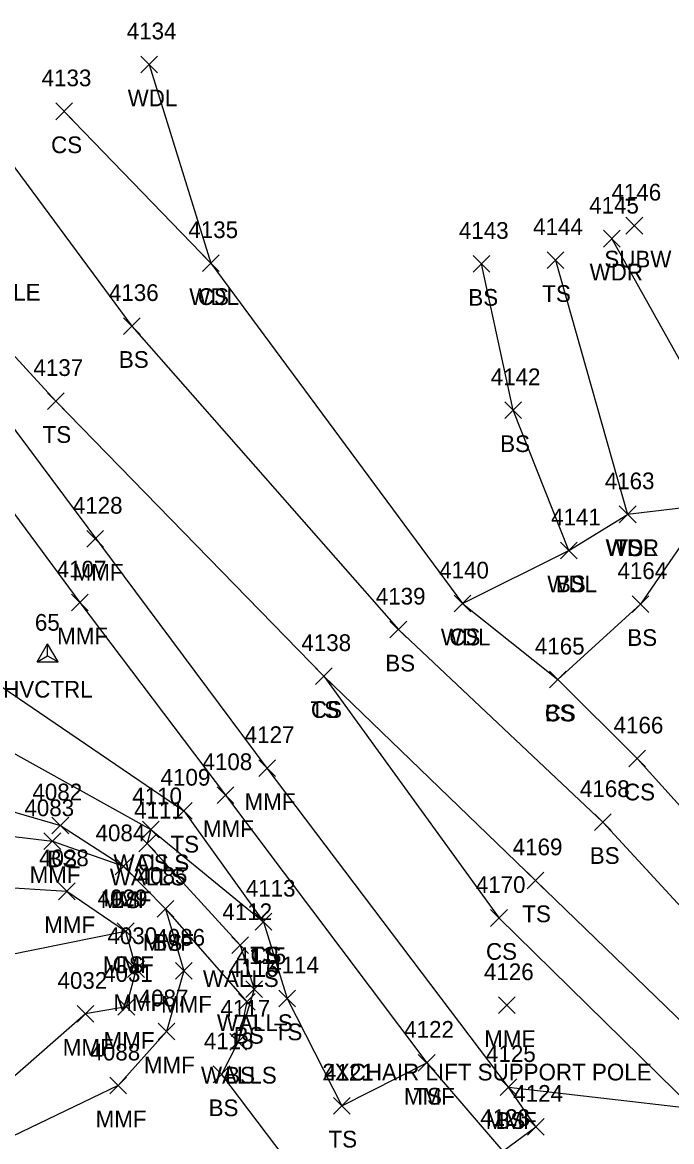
# Model space of a CAD drawing. Extents: x 49137 to 50946, y 9590 to 10709.
# Drawn here: x 50023.9 to 50101.6, y 10574.6 to 10708.5 of the extents above; entities that cross this region are included whole.
import ezdxf

# ---------------------------------------------------------------- set-up
doc = ezdxf.new("R2010")
doc.units = 0
for name, color, linetype in [('C_A', 7, 'Continuous'), ('C_I', 7, 'Continuous'), ('CPSM', 7, 'Continuous'), ('L_A', 7, 'Continuous'), ('L_C', 7, 'Continuous'), ('L_I', 7, 'Continuous'), ('L_TIC', 7, 'Continuous'), ('LAWA', 7, 'Continuous'), ('LDEFAULT', 7, 'Continuous'), ('LELB', 7, 'Continuous'), ('LWS', 7, 'Continuous'), ('U_A', 7, 'Continuous'), ('U_I', 7, 'Continuous'), ('U_TIC', 7, 'Continuous')]:
    doc.layers.add(name, color=color, linetype=linetype)

msp = doc.modelspace()

# ---------------------------------------------------------------- linework, layer by layer
at = {"layer": 'CPSM'}
for p, q in [((50025.71, 10632.03), (50026.96, 10634.2)), ((50028.21, 10632.03), (50026.96, 10634.2)), ((50026.96, 10632.75), (50026.96, 10634.2)), ((50025.71, 10632.03), (50026.96, 10632.75)), ((50025.71, 10632.03), (50028.21, 10632.03)), ((50026.96, 10632.75), (50026.96, 10632.75)), ((50026.96, 10632.75), (50028.21, 10632.03))]:
    msp.add_line(p, q, dxfattribs=at)
at = {"layer": 'L_TIC'}
for points in [[(50038.12, 10702.48), (50040.12, 10704.48)], [(50040.12, 10702.48), (50038.12, 10704.48)], [(50027.94, 10696.87), (50029.94, 10698.87)], [(50029.94, 10696.87), (50027.94, 10698.87)], [(50093.44, 10681.64), (50095.44, 10683.64)], [(50095.44, 10681.64), (50093.44, 10683.64)], [(50045.49, 10678.71), (50047.49, 10680.71)], [(50047.49, 10678.71), (50045.49, 10680.71)], [(50045.49, 10678.71), (50047.49, 10680.71)], [(50047.49, 10678.71), (50045.49, 10680.71)], [(50077.85, 10678.62), (50079.85, 10680.62)], [(50079.85, 10678.62), (50077.85, 10680.62)], [(50086.73, 10679.08), (50088.73, 10681.08)], [(50088.73, 10679.08), (50086.73, 10681.08)], [(50036.05, 10671.19), (50038.05, 10673.19)], [(50038.05, 10671.19), (50036.05, 10673.19)], [(50026.96, 10662.22), (50028.96, 10664.22)], [(50028.96, 10662.22), (50026.96, 10664.22)], [(50081.66, 10661.12), (50083.66, 10663.12)], [(50083.66, 10661.12), (50081.66, 10663.12)], [(50095.35, 10648.67), (50097.35, 10650.67)], [(50097.35, 10648.67), (50095.35, 10650.67)], [(50095.35, 10648.67), (50097.35, 10650.67)], [(50097.35, 10648.67), (50095.35, 10650.67)], [(50095.35, 10648.67), (50097.35, 10650.67)], [(50097.35, 10648.67), (50095.35, 10650.67)], [(50031.67, 10645.75), (50033.67, 10647.75)], [(50033.67, 10645.75), (50031.67, 10647.75)], [(50088.32, 10644.35), (50090.32, 10646.35)], [(50090.32, 10644.35), (50088.32, 10646.35)], [(50088.32, 10644.35), (50090.32, 10646.35)], [(50090.32, 10644.35), (50088.32, 10646.35)], [(50029.82, 10638.12), (50031.82, 10640.12)], [(50031.82, 10638.12), (50029.82, 10640.12)], [(50075.58, 10638), (50077.58, 10640)], [(50077.58, 10638), (50075.58, 10640)], [(50075.58, 10638), (50077.58, 10640)], [(50077.58, 10638), (50075.58, 10640)], [(50096.87, 10637.93), (50098.87, 10639.93)], [(50098.87, 10637.93), (50096.87, 10639.93)], [(50067.92, 10634.88), (50069.92, 10636.88)], [(50069.92, 10634.88), (50067.92, 10636.88)], [(50059.02, 10629.32), (50061.02, 10631.32)], [(50061.02, 10629.32), (50059.02, 10631.32)], [(50059.02, 10629.32), (50061.02, 10631.32)], [(50061.02, 10629.32), (50059.02, 10631.32)], [(50086.99, 10628.91), (50088.99, 10630.91)], [(50088.99, 10628.91), (50086.99, 10630.91)], [(50086.99, 10628.91), (50088.99, 10630.91)], [(50088.99, 10628.91), (50086.99, 10630.91)], [(50096.47, 10619.46), (50098.47, 10621.46)], [(50098.47, 10619.46), (50096.47, 10621.46)], [(50052.24, 10618.32), (50054.24, 10620.32)], [(50054.24, 10618.32), (50052.24, 10620.32)], [(50047.26, 10615.08), (50049.26, 10617.08)], [(50049.26, 10615.08), (50047.26, 10617.08)], [(50042.26, 10613.22), (50044.26, 10615.22)], [(50044.26, 10613.22), (50042.26, 10615.22)], [(50027.49, 10611.46), (50029.49, 10613.46)], [(50029.49, 10611.46), (50027.49, 10613.46)], [(50092.38, 10611.86), (50094.38, 10613.86)], [(50094.38, 10611.86), (50092.38, 10613.86)], [(50038.3, 10610.99), (50040.3, 10612.99)], [(50040.3, 10610.99), (50038.3, 10612.99)], [(50038.3, 10610.99), (50040.3, 10612.99)], [(50040.3, 10610.99), (50038.3, 10612.99)], [(50026.53, 10609.57), (50028.53, 10611.57)], [(50028.53, 10609.57), (50026.53, 10611.57)], [(50037.87, 10609.29), (50039.87, 10611.29)], [(50039.87, 10609.29), (50037.87, 10611.29)], [(50035.04, 10606.57), (50037.04, 10608.57)], [(50037.04, 10606.57), (50035.04, 10608.57)], [(50035.04, 10606.57), (50037.04, 10608.57)], [(50037.04, 10606.57), (50035.04, 10608.57)], [(50084.34, 10604.89), (50086.34, 10606.89)], [(50086.34, 10604.89), (50084.34, 10606.89)], [(50028.28, 10603.58), (50030.28, 10605.58)], [(50030.28, 10603.58), (50028.28, 10605.58)], [(50040.07, 10601.47), (50042.07, 10603.47)], [(50042.07, 10601.47), (50040.07, 10603.47)], [(50040.07, 10601.47), (50042.07, 10603.47)], [(50042.07, 10601.47), (50040.07, 10603.47)], [(50079.96, 10600.39), (50081.96, 10602.39)], [(50081.96, 10600.39), (50079.96, 10602.39)], [(50051.79, 10599.95), (50053.79, 10601.95)], [(50053.79, 10599.95), (50051.79, 10601.95)], [(50051.79, 10599.95), (50053.79, 10601.95)], [(50053.79, 10599.95), (50051.79, 10601.95)], [(50035.3, 10598.8), (50037.3, 10600.8)], [(50037.3, 10598.8), (50035.3, 10600.8)], [(50035.3, 10598.8), (50037.3, 10600.8)], [(50037.3, 10598.8), (50035.3, 10600.8)], [(50049, 10597.14), (50051, 10599.14)], [(50051, 10597.14), (50049, 10599.14)], [(50036.54, 10594.27), (50038.54, 10596.27)], [(50038.54, 10594.27), (50036.54, 10596.27)], [(50042.25, 10594.08), (50044.25, 10596.08)], [(50044.25, 10594.08), (50042.25, 10596.08)], [(50050.68, 10591.87), (50052.68, 10593.87)], [(50052.68, 10591.87), (50050.68, 10593.87)], [(50035.38, 10589.75), (50037.38, 10591.75)], [(50037.38, 10589.75), (50035.38, 10591.75)], [(50049.81, 10590.35), (50051.81, 10592.35)], [(50051.81, 10590.35), (50049.81, 10592.35)], [(50054.61, 10590.77), (50056.61, 10592.77)], [(50056.61, 10590.77), (50054.61, 10592.77)], [(50080.9, 10589.96), (50082.9, 10591.96)], [(50082.9, 10589.96), (50080.9, 10591.96)], [(50030.49, 10588.92), (50032.49, 10590.92)], [(50032.49, 10588.92), (50030.49, 10590.92)], [(50040.2, 10586.82), (50042.2, 10588.82)], [(50042.2, 10586.82), (50040.2, 10588.82)], [(50048.76, 10585.59), (50050.76, 10587.59)], [(50050.76, 10585.59), (50048.76, 10587.59)], [(50048.76, 10585.59), (50050.76, 10587.59)], [(50050.76, 10585.59), (50048.76, 10587.59)], [(50071.31, 10583.07), (50073.31, 10585.07)], [(50073.31, 10583.07), (50071.31, 10585.07)], [(50071.31, 10583.07), (50073.31, 10585.07)], [(50073.31, 10583.07), (50071.31, 10585.07)], [(50046.77, 10581.69), (50048.77, 10583.69)], [(50048.77, 10581.69), (50046.77, 10583.69)], [(50034.42, 10580.35), (50036.42, 10582.35)], [(50036.42, 10580.35), (50034.42, 10582.35)], [(50081.1, 10580.17), (50083.1, 10582.17)], [(50083.1, 10580.17), (50081.1, 10582.17)], [(50081.1, 10580.17), (50083.1, 10582.17)], [(50083.1, 10580.17), (50081.1, 10582.17)], [(50061.16, 10577.94), (50063.16, 10579.94)], [(50063.16, 10577.94), (50061.16, 10579.94)], [(50084.37, 10575.41), (50086.37, 10577.41)], [(50086.37, 10575.41), (50084.37, 10577.41)]]:
    msp.add_lwpolyline(points, dxfattribs=at)
at = {"layer": 'LAWA'}
for points in [[(50039.12, 10703.48), (50046.49, 10679.71), (50076.58, 10639), (50089.32, 10645.35), (50096.35, 10649.67)], [(50094.44, 10682.64), (50106.82, 10660.55), (50106.07, 10650.82), (50096.35, 10649.67)]]:
    msp.add_lwpolyline(points, dxfattribs=at)
at = {"layer": 'LDEFAULT'}
for points in [[(49999.81, 10680.44), (50019.05, 10655.01), (50030.82, 10639.12), (50048.26, 10616.08), (50072.31, 10584.07), (50081.41, 10573.52), (50085.37, 10576.41), (50082.1, 10581.17), (50053.24, 10619.32), (50004.68, 10684.45)], [(49979.71, 10673.25), (49982.06, 10666.2), (49980.02, 10657.8), (49976.48, 10651.25), (49969.19, 10644.01), (49964.08, 10636.25), (49961.24, 10632.4), (49957.74, 10623.46), (49959, 10617.9), (49962.44, 10614.3), (49969, 10611.78), (49980.82, 10611.25), (49985, 10612.56), (49999.5, 10612.61), (50013.59, 10612.25), (50027.53, 10610.57), (50036.04, 10607.57), (50041.07, 10602.47), (50043.25, 10595.08), (50041.2, 10587.82), (50035.42, 10581.35), (50016.39, 10572.24)], [(49976.24, 10663.17), (49971.17, 10652.6), (49967.44, 10647.97), (49961.54, 10640.89), (49959.06, 10637.47), (49953.41, 10627.75), (49954.03, 10615.14), (49965.28, 10607.03), (49984.97, 10604.55), (50003.36, 10604.43), (50020.33, 10605.17), (50029.28, 10604.58), (50036.3, 10599.8), (50037.54, 10595.27), (50036.38, 10590.75), (50031.49, 10589.92), (50020.38, 10580.2), (50008.1, 10574.44)]]:
    msp.add_lwpolyline(points, dxfattribs=at)
at = {"layer": 'LELB'}
for points in [[(50028.94, 10697.87), (50046.49, 10679.71)], [(50019.73, 10695.53), (50037.05, 10672.19), (50068.92, 10635.88), (50093.38, 10612.86), (50116.43, 10587.84), (50130.03, 10572.43), (50130.75, 10559.66)], [(50109.59, 10691.77), (50123.16, 10663.21), (50113.81, 10660.27), (50106.07, 10650.82), (50097.87, 10638.93), (50087.99, 10629.91)], [(50006.39, 10686.67), (50027.96, 10663.22), (50060.02, 10630.32), (50085.34, 10605.89), (50109.29, 10582.73), (50124.77, 10564.49)], [(50087.73, 10680.08), (50096.35, 10649.67)], [(50089.32, 10645.35), (50082.66, 10662.12), (50078.85, 10679.62)], [(49993.04, 10675.61), (50002.74, 10646.68), (50016.93, 10632.09), (50043.26, 10614.22), (50052.79, 10600.95), (50055.61, 10591.77), (50062.16, 10578.94), (50072.31, 10584.07)], [(49982.06, 10666.2), (49991.76, 10644), (50012.12, 10627.08), (50039.3, 10611.99), (50052.79, 10600.95)], [(50076.58, 10639), (50087.99, 10629.91), (50097.47, 10620.46), (50116.3, 10599.61), (50123.36, 10595.45), (50134.59, 10584.36), (50132.63, 10576.14), (50142.17, 10562.63), (50154.37, 10552.18), (50169.69, 10532.5), (50175.83, 10519.81), (50190.78, 10509.78), (50196.23, 10504.34)], [(50060.02, 10630.32), (50080.96, 10601.39), (50104.18, 10578.62)], [(49998.8, 10622.94), (50014.62, 10616.48), (50028.49, 10612.46), (50036.04, 10607.57)], [(50041.07, 10602.47), (50050.81, 10591.35), (50049.76, 10586.59), (50047.77, 10582.69), (50059.45, 10567.23), (50076.26, 10569.21), (50081.41, 10573.52)], [(49951.21, 10484.84), (49950.27, 10514.68), (49954.83, 10538.34), (49978.78, 10566.92), (49984.02, 10579.77), (50007.67, 10594.03), (50036.3, 10599.8)], [(50082.1, 10581.17), (50104.18, 10578.62), (50124.77, 10564.49), (50130.75, 10559.66), (50131.35, 10557.79)]]:
    msp.add_lwpolyline(points, dxfattribs=at)
at = {"layer": 'LWS'}
msp.add_lwpolyline([(50039.3, 10611.99), (50038.87, 10610.29), (50050, 10598.14), (50051.68, 10592.87), (50049.76, 10586.59)], dxfattribs=at)
at = {"layer": 'U_TIC'}
for points in [[(50096.15, 10683.2), (50098.15, 10685.2)], [(50098.15, 10683.2), (50096.15, 10685.2)]]:
    msp.add_lwpolyline(points, dxfattribs=at)

# ---------------------------------------------------------------- texts
at = {"layer": 'C_A'}
msp.add_text('HVCTRL', height=2, dxfattribs=at).set_placement((50021.65, 10627.75))
at = {"layer": 'C_I'}
msp.add_text('65', height=2, dxfattribs=at).set_placement((50025.44, 10635.75))
at = {"layer": 'L_A'}
for s, p in [('WDL', (50036.54, 10698.48)), ('CS', (50027.38, 10692.87)), ('WDR', (50091.8, 10677.64)), ('WDL', (50043.91, 10674.71)), ('CS', (50044.94, 10674.71)), ('BS', (50077.29, 10674.62)), ('TS', (50086.14, 10675.08)), ('BS', (50035.49, 10667.19)), ('TS', (50026.37, 10658.22)), ('BS', (50081.1, 10657.12)), ('WDR', (50093.71, 10644.67)), ('WDL', (50093.77, 10644.67)), ('TS', (50094.76, 10644.67)), ('MMF', (50029.96, 10641.75)), ('WDL', (50086.73, 10640.35)), ('BS', (50087.76, 10640.35)), ('MMF', (50028.1, 10634.12)), ('WDL', (50074, 10634)), ('CS', (50075.02, 10634)), ('BS', (50096.31, 10633.93)), ('BS', (50067.36, 10630.88)), ('TS', (50058.42, 10625.32)), ('CS', (50058.46, 10625.32)), ('CS', (50086.43, 10624.91)), ('BS', (50086.43, 10624.91)), ('CS', (50095.91, 10615.46)), ('MMF', (50050.52, 10614.32)), ('MMF', (50045.55, 10611.08)), ('TS', (50041.67, 10609.22)), ('BS', (50026.93, 10607.46)), ('WALLS', (50034.84, 10606.99)), ('CS', (50037.74, 10606.99)), ('BS', (50091.82, 10607.86)), ('MMF', (50024.81, 10605.57)), ('WALLS', (50034.41, 10605.29)), ('MMF', (50033.32, 10602.57)), ('BS', (50034.48, 10602.57)), ('TS', (50083.75, 10600.89)), ('MMF', (50026.56, 10599.58)), ('MMF', (50038.36, 10597.47)), ('BS', (50039.51, 10597.47)), ('CS', (50079.4, 10596.39)), ('TS', (50051.2, 10595.95)), ('CS', (50051.23, 10595.95)), ('MMF', (50033.58, 10594.8)), ('CS', (50034.74, 10594.8)), ('WALLS', (50045.54, 10593.14)), ('MMF', (50034.83, 10590.27)), ('MMF', (50040.53, 10590.08)), ('WALLS', (50047.22, 10587.87)), ('MMF', (50033.66, 10585.75)), ('BS', (50049.25, 10586.35)), ('TS', (50054.02, 10586.77)), ('MMF', (50079.19, 10585.96)), ('MMF', (50028.78, 10584.92)), ('MMF', (50038.48, 10582.82)), ('WALLS', (50045.31, 10581.59)), ('BS', (50048.2, 10581.59)), ('MMF', (50069.59, 10579.07)), ('TS', (50070.72, 10579.07)), ('BS', (50046.22, 10577.69)), ('MMF', (50032.71, 10576.35)), ('MMF', (50079.38, 10576.17)), ('BS', (50080.54, 10576.17)), ('TS', (50060.57, 10573.94))]:
    msp.add_text(s, height=2, dxfattribs=at).set_placement(p)
at = {"layer": 'L_C'}
for p in [(49986.74, 10675.23), (50059.83, 10581.96)]:
    msp.add_text('2XCHAIR LIFT SUPPORT POLE', height=2, dxfattribs=at).set_placement(p)
at = {"layer": 'L_I'}
for s, p in [('4134', (50036.43, 10706.48)), ('4133', (50026.25, 10700.87)), ('4145', (50091.74, 10685.64)), ('4135', (50043.8, 10682.71)), ('4135', (50043.8, 10682.71)), ('4143', (50076.16, 10682.62)), ('4144', (50085.04, 10683.08)), ('4136', (50034.3, 10675.19)), ('4137', (50025.27, 10666.22)), ('4142', (50079.97, 10665.12)), ('4163', (50093.61, 10652.67)), ('4163', (50093.61, 10652.67)), ('4163', (50093.61, 10652.67)), ('4128', (50029.98, 10649.75)), ('4141', (50087.19, 10648.35)), ('4141', (50087.19, 10648.35)), ('4107', (50028.05, 10642.12)), ('4140', (50073.8, 10642)), ('4140', (50073.8, 10642)), ('4164', (50095.13, 10641.93)), ('4139', (50066.22, 10638.88)), ('4138', (50057.32, 10633.32)), ('4138', (50057.32, 10633.32)), ('4165', (50085.25, 10632.91)), ('4165', (50085.25, 10632.91)), ('4166', (50094.67, 10623.46)), ('4127', (50050.54, 10622.32)), ('4108', (50045.49, 10619.08)), ('4109', (50040.48, 10617.22)), ('4082', (50025.15, 10615.46)), ('4168', (50090.64, 10615.86)), ('4110', (50037.09, 10614.99)), ('4110', (50037.09, 10614.99)), ('4083', (50024.19, 10613.57)), ('4111', (50037.31, 10613.29)), ('4084', (50032.7, 10610.57)), ('4084', (50032.7, 10610.57)), ('4169', (50082.6, 10608.89)), ('4028', (50025.94, 10607.58)), ('4085', (50037.73, 10605.47)), ('4085', (50037.73, 10605.47)), ('4170', (50078.18, 10604.39)), ('4113', (50050.67, 10603.95)), ('4113', (50050.67, 10603.95)), ('4029', (50032.95, 10602.8)), ('4029', (50032.95, 10602.8)), ('4112', (50047.87, 10601.14)), ('4030', (50034.12, 10598.27)), ('4086', (50039.85, 10598.08)), ('4115', (50049.55, 10595.87)), ('4031', (50033.6, 10593.75)), ('4116', (50048.62, 10594.35)), ('4114', (50053.48, 10594.77)), ('4126', (50079.16, 10593.96)), ('4032', (50028.15, 10592.92)), ('4087', (50037.86, 10590.82)), ('4117', (50047.64, 10589.59)), ('4117', (50047.64, 10589.59)), ('4122', (50069.62, 10587.07)), ('4122', (50069.62, 10587.07)), ('4118', (50045.65, 10585.69)), ('4088', (50032.09, 10584.35)), ('4125', (50079.41, 10584.17)), ('4125', (50079.41, 10584.17)), ('4121', (50060.03, 10581.94)), ('4124', (50082.67, 10579.41)), ('4123', (50078.72, 10576.52)), ('4123', (50078.72, 10576.52))]:
    msp.add_text(s, height=2, dxfattribs=at).set_placement(p)
at = {"layer": 'U_A'}
msp.add_text('SUBW', height=2, dxfattribs=at).set_placement((50093.56, 10679.2))
at = {"layer": 'U_I'}
msp.add_text('4146', height=2, dxfattribs=at).set_placement((50094.41, 10687.2))

doc.saveas('drawing.dxf')
